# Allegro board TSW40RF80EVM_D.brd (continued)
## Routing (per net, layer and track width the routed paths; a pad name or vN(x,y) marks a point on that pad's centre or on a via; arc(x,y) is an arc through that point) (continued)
V1: length 82.4
  TOP w0.203: U29.1 22.45,60.68 v3(22.53,60.76) ; U30.1 v3(22.4,58.39)
  L4_SIG w0.127: v3(22.53,60.76) 22.53,58.52 v3(22.4,58.39) 22.4,57.94 24.72,55.62 24.72,48.53 v1(25.65,47.6)
  L6_SIG w0.127: JP3.1 79.51,51.23 78.73,52.01 69.38,52.01 69.15,51.78 69.15,51.75 68.95,51.55 68.92,51.55 68.81,51.44 66.14,51.44 62.51,47.8 58.85,47.8 58.04,46.99 56.29,46.99 55.02,48.26 50.87,48.26 50.68,48.07 50.31,48.07 50.12,48.26 47.75,48.26 47.35,47.85 43.99,47.85 43.1,46.96 43.1,45.49 41.05,43.43 41.05,43.41 39.7,42.06 32.56,42.06 32.13,42.49 32.11,42.49 31.29,43.31 26.06,43.31 25.22,44.15 25.22,44.88 25.98,45.64 25.98,47.27 v1(25.65,47.6)
  BOTTOM w0.127: R38.2 79.52,51.26 JP3.1
V2: length 78.9
  TOP w0.127: v1(23.72,48.41) 23.75,48.44 28.32,48.44 31.62,45.14 38.4,45.14 38.71,44.83 38.71,44.48 39.17,44.02 43.71,44.02 44.78,42.95 44.78,42.37 45.09,42.06 48.79,42.06 49.2,42.47 58.7,42.47 61.54,39.62 64.54,39.62 64.85,39.93 71.65,39.93 74.22,42.49 74.22,45.59 75.23,46.61 78.93,46.61 JP3.3
  TOP w0.203: U30.5 v3(22.05,56.59) ; U29.5 v3(22.12,58.9)
  L4_SIG w0.127: v3(22.12,58.9) 22.02,58.8 22.02,58.22 21.67,57.86 21.67,56.97 v3(22.05,56.59) 23.24,55.4 23.24,48.9 v1(23.72,48.41)
  BOTTOM w0.127: R39.2 79.46,47.14 JP3.3
V3: length 87.6
  TOP w0.203: v3(23.83,58.19) 24.11,57.91 U28.1 ; v3(23.62,60.83) 24.16,60.29 U27.1
  L4_SIG w0.127: v3(23.62,60.83) 23.62,58.39 v3(23.83,58.19) 24.49,57.53 24.49,56.77 25.15,56.11 25.15,49 v1(25.2,48.95)
  L6_SIG w0.127: v1(25.2,48.95) 24.74,48.49 24.74,40.94 25.27,40.41 25.27,39.12 26.39,38 27.18,38 27.51,38.33 28.12,38.33 28.47,37.97 32.26,37.97 32.74,37.49 38.51,37.49 39.73,36.27 43.97,36.27 46.76,39.07 52.04,39.07 52.4,39.42 78.94,39.42 80.01,40.49 80.01,43.33 JP7.1
  BOTTOM w0.127: R214.2 81.04,44.37 JP7.1
V4: length 75.7
  TOP w0.127: JP7.3 80.13,39.45 65.28,39.45 65,39.17 60.63,39.17 57.7,42.1 49.44,42.1 49.02,41.68 44.96,41.68 44.27,42.37 44.27,42.95 43.61,43.61 41.02,43.61 40.51,43.1 39,43.1 38.73,43.36 38.73,43.68 38.35,44.07 32.11,44.07 28.17,48.01 v1(26.37,48.01)
  TOP w0.203: U27.5 v3(25.78,59.94) ; U28.5 v3(25.78,57.56)
  L4_SIG w0.127: v1(26.37,48.01) 26.06,48.31 26.06,50.11 26.48,50.54 26.48,55.97 26.48,55.98 26.48,56.34 26.48,56.35 26.48,56.68 25.78,57.38 v3(25.78,57.56) 25.25,58.09 25.25,59.55 25.65,59.94 v3(25.78,59.94)
  BOTTOM w0.127: R213.2 81.04,40.39 JP7.3
V5: length 90
  TOP w0.203: v3(27.79,58.75) 27.78,58.74 U4.1 ; v3(28.07,60.68) 28.06,60.67 U3.1
  L4_SIG w0.127: v1(27.48,34.54) 27.48,35.74 29.77,38.02 29.77,40.51 28.12,42.16 28.12,47.07 28.32,47.27 28.32,57.48 27.79,58.01 v3(27.79,58.75) 28.07,59.03 v3(28.07,60.68)
  L6_SIG w0.127: v1(27.48,34.54) 31.05,34.54 32.25,35.75 32.27,35.75 32.97,36.45 37.34,36.45 38.1,35.69 51.89,35.69 55.12,38.91 69.77,38.91 73.23,35.46 78.21,35.46 79.5,36.75 81.84,36.75 82.54,37.46 JP8.1
  BOTTOM w0.127: JP8.1 82.67,37.47 R216.2
V6: length 81.1
  TOP w0.127: JP8.3 82.61,33.53 81.33,33.53 77.39,37.47 73.56,37.47 72.11,38.91 65.81,38.91 65.53,38.63 60.45,38.63 57.84,41.25 50.67,41.25 50.55,41.12 49.76,41.12 49.56,41.33 44.68,41.33 43.8,42.2 43.8,42.84 43.56,43.08 41.1,43.08 40.72,42.7 40.21,42.7 39.29,41.78 33.81,41.78 33.58,41.55 31.11,41.55 30.63,42.04 30.63,44.98 28.07,47.55 v1(26.97,47.55)
  TOP w0.203: U3.5 v3(27.41,59.31) ; U4.5 v3(27.43,56.95)
  L4_SIG w0.127: v3(27.41,59.31) 27.15,59.56 26.79,59.56 26.43,59.2 26.43,58.43 27.43,57.43 v3(27.43,56.95) 27.79,56.59 27.79,53.88 27.97,53.7 27.97,53.42 27.79,53.24 27.79,49.5 26.97,48.69 v1(26.97,47.55)
  BOTTOM w0.127: JP8.3 82.67,33.45 R215.2
1P8V:
  vias: v1(32.72,10.69) v1(32.72,9.63) v1(33.71,10.69) v1(33.71,9.63) v1(34.75,10.72) v1(34.75,9.65) v1(35.71,10.72) v1(35.71,9.65) v1(75.54,10.97) v1(75.54,9.98) v1(75.56,8.94) v1(75.56,7.98) v1(76.61,10.97) v1(76.61,9.98) v1(76.63,8.94) v1(76.63,7.98)
3P3VAUX: length 15.9
  L8_SIG w0.127: v1(149.96,19.81) 150.55,20.4 150.55,21.67 151.89,23.01 151.89,23.65 153.59,25.35 153.85,25.35 155.09,26.59 155.09,32.56 v1(155.68,33.15)
+1P0V_ANA: length 63.7
  L3_PWR_SIG w0.305: v1(15.05,24.07) 15.25,24.07 15.27,24.05
  L10_PWR_SIG w0.102: v1(15.05,26.47) 15.3,26.47 15.7,26.87 16.13,26.87 16.26,27 16.26,27.43 16.48,27.66 16.79,27.66 17.07,27.94 17.07,29.22
  L10_PWR_SIG w0.127: 17.07,29.22 17.59,29.74 22.25,29.74 23.34,28.65 47.62,28.65 48.13,28.14 48.13,27.51 50.24,25.4 50.39,25.4 52.1,23.7 52.91,23.7 55.04,21.56 55.04,21.08 55.68,20.45 56.29,20.45 59.46,17.27 59.46,8.86 60.55,7.77 v1(60.55,6.81)
  vias: v1(15.06,31.88) v1(16.26,32.99) v1(43.21,14.43) v1(43.21,13.41) v1(44.35,14.43) v1(44.35,13.41) v1(45.49,14.43) v1(45.49,13.41) v1(46.63,14.43) v1(46.63,13.41) v1(47.78,14.43) v1(47.78,13.41)
+1P0V_CLK: length 1.2
  L10_PWR_SIG w0.305: v1(15.85,25.67) v1(16.65,25.67)
  BOTTOM w0.305: C66.1 15.85,24.87 v1(15.85,24.87) ; C53.1 16.66,25.68 v1(16.65,25.67) ; v1(15.85,25.67) 15.88,25.69 C65.1 ; C54.1 16.66,24.86 v1(16.65,24.87)
  vias: v1(17.45,23.27) v1(17.45,22.47) v1(19.05,20.87) v1(31.45,6.99) v1(31.5,8) v1(32.44,8) v1(32.38,6.99) v1(33.4,6.99) v1(33.45,8) v1(34.54,6.99) v1(34.59,8) v1(35.74,8) v1(35.69,6.99)
+1P0V_DIG: length 7.2
  L3_PWR_SIG w0.102: 21.84,25.48 21.64,25.27 21.29,25.27 21.08,25.48 21.06,25.48 20.85,25.27 20.5,25.27 20.32,25.45 20.27,25.45 20.09,25.27 19.68,25.27 19.61,25.35 19.51,25.35 ; 18.08,24.49 17.86,24.71 17.86,25.04 18.11,25.3
  BOTTOM w0.305: v1(19.05,26.47) v1(18.25,25.67) v1(19.05,24.87) v1(18.25,24.07)
  vias: v1(38.48,10.92) v1(38.48,9.78) v1(39.62,10.92) v1(39.62,9.78) v1(40.89,10.92) v1(40.89,9.78) v1(42.16,10.92) v1(42.16,9.78) v1(43.43,10.92) v1(43.43,9.78)
+1P0V_VDDL1: length 3.4
  L3_PWR_SIG w0.102: 18.95,27.69 19.23,27.69 19.46,27.91 19.46,28.27 ; 17.58,26.11 17.65,26.11 17.86,26.31 17.86,26.62 17.75,26.72 17.75,26.85 ; 18.26,26.87 18.41,26.87 18.64,27.1 18.64,27.36
  BOTTOM w0.305: v1(17.45,24.87) 17.45,24.88 C62.1 ; v1(21.45,25.67) 21.6,25.52 21.6,25.46 ; C61.1 17.45,25.75 v1(17.45,25.67) ; v1(21.45,26.47) 21.58,26.6 C49.1
  vias: v1(36.88,14.45) v1(36.88,13.56) v1(36.88,12.57) v1(36.88,11.71) v1(37.77,14.45) v1(37.77,13.56) v1(37.77,12.57) v1(37.77,11.71)
A_IN: length 14.2
  TOP w0.381: C160.1 12.7,47.86 arc(11.01,46.73) 9.02,46.33 J9.1
ADC_CLK: length 1.4
  TOP w0.381: J8.1 C153.1
ADC_CLKINM: length 1.5
  TOP w0.203: U2.28 30.31,58.3 R229.1
  TOP w0.305: C428.2 R229.1
ADC_CLKINP: length 1.5
  TOP w0.203: U2.27 30.31,58.8 R229.2
  TOP w0.305: C427.2 R229.2
ADC_LKXEN: length 0.7
  TOP w0.254: U28.6 25.5,58.22 C434.1
ADC_LKXEP: length 0.7
  TOP w0.254: C433.1 25.45,60.55 U27.6
ADC_LXEN: length 0.6
  TOP w0.254: C432.1 22.99,56.95 U30.6
ADC_LXEP: length 0.6
  TOP w0.254: C431.1 23.03,59.29 U29.6
ADC_RESET: length 98.3
  TOP w0.127: v1(59.49,49.05) 59.03,49.05 55.44,52.64 49.09,52.64 47.96,51.51 v1(47.96,51.26) ; v1(38.43,50.83) 38.43,51.13 37.69,51.87 37.69,53.04 37.29,53.44 U2.48 ; v1(97.08,8.89) 97.11,8.92 SW2.2
  L4_SIG w0.127: v1(97.08,8.89) 97.08,10.62 96.32,11.38 96.32,19.94 95.73,20.52 87.51,20.52 86.82,21.22 86.82,25.3 86.33,25.78 86.33,31.93 85.27,32.99 v3(85.27,36.58) 85.27,36.59 84.71,37.15 84.71,37.87 83.67,38.91 79.4,38.91 76.25,42.06 67.77,42.06 61.21,48.62 59.92,48.62 v1(59.49,49.05)
  BOTTOM w0.127: v1(47.96,51.26) 47.75,51.46 43.21,51.46 42.93,51.18 38.79,51.18 v1(38.43,50.83)
ADC_SCLK: length 75.8
  TOP w0.127: U2.6 v3(37.79,63.57)
  L6_SIG w0.127: v1(81.1,67.11) 81.05,67.06 80.57,67.06 78.74,65.23 42.16,65.23 40.04,63.1 38.26,63.1 v3(37.79,63.57)
  BOTTOM w0.127: v3(86.13,39.17) 84.07,41.22 84.07,50.29 83.31,51.05 83.31,56.34 81.65,58 81.65,58.66 82.25,59.26 82.25,60.4 81.92,60.73 81.92,62 81.74,62.18 81.74,63.83 81.1,64.46 v1(81.1,67.11)
ADC_SDIO: length 76
  TOP w0.127: U2.5 38.29,63.82 38.18,63.93 v3(38.18,64.44)
  L6_SIG w0.127: v3(38.18,64.44) 38.58,64.03 40.03,64.03 41.73,65.74 78.21,65.74 v1(79.63,67.16)
  BOTTOM w0.127: v3(85.27,38.08) 84.86,38.08 83.06,39.88 83.06,50.67 82.46,51.27 82.46,54.52 80.11,56.87 80.11,58.75 79.65,59.21 79.65,61.7 80.14,62.18 80.14,63.96 79.88,64.21 79.88,66.9 v1(79.63,67.16)
ADC_SDO: length 79.6
  TOP w0.127: v1(35.1,64.92) 35.29,64.73 U2.11
  L6_SIG w0.127: v1(78.38,67.16) 77.97,67.58 76.62,67.58 76.43,67.39 36.96,67.39 36.17,66.6 36.17,65.99 v1(35.1,64.92)
  BOTTOM w0.127: v3(85.27,37.58) 84.75,37.58 82.55,39.78 82.55,50.36 81.98,50.93 81.98,53.73 78.97,56.74 78.97,58.17 78.42,58.71 78.42,62.22 78.85,62.65 78.85,63.44 78.56,63.73 78.56,66.98 v1(78.38,67.16)
ADC_SEN: length 75.9
  TOP w0.127: U2.7 37.29,64.09 v1(37.57,64.36)
  L6_SIG w0.127: v1(37.57,64.36) 37.73,64.53 37.75,64.53 38.93,65.71 39.57,65.71 40.72,66.85 76.96,66.85 v1(77.24,67.13)
  BOTTOM w0.127: v1(77.24,67.13) 77.24,63.65 76.8,63.21 76.8,60.97 77.42,60.35 77.42,57 81.05,53.37 81.05,51.09 82.04,50.1 82.04,39.75 84.63,37.16 85.19,37.16 v3(85.27,37.08)
ADC_SYNC_N: length 128.9
  L6_SIG w0.127: v1(146.76,44.53) 146.56,44.32 145.26,44.32 144.83,44.75 144.83,44.81 144.53,45.11 144.47,45.11 143.1,46.48 143.1,53.11 137.82,58.39 136.58,58.39 135.94,57.76 134.21,57.76 133.15,58.83 46.71,58.83 43.59,55.7 40.87,55.7 40.81,55.64 40.8,55.64 40.28,55.12 32.92,55.12 32.13,54.33 31.57,54.33 31.51,54.28 v3(31.14,54.28)
  BOTTOM w0.102: v1(146.76,44.53) 146.18,43.94 J14.G13
ADC_SYNC_P: length 128.9
  L6_SIG w0.127: v3(31.14,54.8) 31.52,54.79 31.55,54.76 31.95,54.76 32.74,55.55 40.08,55.55 40.61,56.08 40.64,56.08 40.69,56.13 43.38,56.13 46.51,59.26 133.33,59.26 134.39,58.19 135.76,58.19 136.4,58.83 138,58.83 143.54,53.29 143.54,48.62 143.65,48.51 143.83,48.51 143.94,48.39 143.94,48.24 143.83,48.12 143.65,48.12 143.54,48.01 143.54,46.66 144,46.19 144.16,46.19 144.31,46.34 144.46,46.34 144.58,46.23 144.58,46.07 144.43,45.92 144.43,45.77 144.65,45.54 144.73,45.54 145.26,45.01 145.26,44.93 145.44,44.75 145.97,44.75 146.18,44.96 v1(146.18,45.21)
  BOTTOM w0.102: J14.G12 v1(146.18,45.21)
ADC_SYSREFN: length 27.6
  TOP w0.203: U2.34 30.94,55.3 30.79,55.44 29.92,55.44 29.88,55.47 v1(29.64,55.47)
  L6_SIG w0.127: v1(35.23,50.37) 35.08,50.52 35.08,51.23 34.19,52.12 32.38,52.12 30.89,50.62 30.89,49 30.07,48.18 30.07,45.95 29.51,45.39 29.18,45.39 29,45.57 28.8,45.57 28.62,45.39 28.3,45.39 27.91,45.77 27.91,46.58 28.03,46.69 28.16,46.69 28.27,46.8 28.27,46.96 28.16,47.07 28.03,47.07 27.91,47.19 27.91,52.67 28.98,53.74 28.98,54.44 29.09,54.56 29.15,54.56 29.26,54.67 29.26,54.82 29.15,54.94 29.09,54.94 28.98,55.05 28.98,55.35 29.2,55.56 29.55,55.56 v1(29.64,55.47)
  BOTTOM w0.203: R99.2 35.23,49.76 v1(35.23,50.37)
ADC_SYSREFP: length 27.6
  TOP w0.203: U2.33 30.06,55.8 29.78,56.08 v1(29.64,56.08)
  L6_SIG w0.127: v1(34.53,50.39) 34.65,50.51 34.65,51.05 34.51,51.19 34.2,51.19 34.08,51.32 34.08,51.62 34.01,51.69 32.56,51.69 31.32,50.44 31.32,48.82 30.51,48 30.51,45.77 29.69,44.96 28.12,44.96 27.48,45.59 27.48,52.85 28.55,53.92 28.55,55.53 29.02,55.99 29.55,55.99 v1(29.64,56.08)
  BOTTOM w0.203: v1(34.53,50.39) 34.53,49.74 R96.2
AIN+: length 4.1
  TOP w0.381: C162.1 T5.1 T4.3 R55.2
AIN-: length 4.1
  TOP w0.381: C158.1 T5.3 T4.1 R54.2
AINM: length 9.9
  TOP w0.305: U2.41 33.79,53
  TOP w0.381: 33.79,53 33.77,52.98 33.77,52.26 33.3,51.79 32.78,51.79 32.62,51.95 32.62,52.07 32.46,52.22 32.24,52.22 31.87,51.85 31.28,51.85 30.84,52.3 30.3,52.3 29.79,51.79 29.18,51.79 28.14,52.83 T5.4 C158.2
AINP: length 10
  TOP w0.305: U2.42 34.29,53.27 34.3,53.26 34.3,52.84
  TOP w0.381: 34.3,52.84 34.3,52.06 33.53,51.28 29.13,51.28 28.14,50.29 T5.6 C162.2
ALARM: length 9.1
  TOP w0.102: v1(17.45,27.27) 17.04,27.69 17.04,29.22
  TOP w0.127: 17.04,29.22 15.35,30.91 13.72,30.91 TP3.1
ATEST: length 13
  L8_SIG w0.102: 13.92,22.05 16.97,22.05 17.34,21.67 v1(17.45,21.67)
  L8_SIG w0.127: TP15.1 6.17,25.27 9.4,22.05 11.79,22.05 11.99,22.25 12.34,22.25 12.55,22.05 13.92,22.05
B_IN: length 15.3
  TOP w0.381: J10.1 6.13,60.33 arc(8.21,60.74) 9.98,61.92 14.96,66.9 C164.1
BIN+: length 4.1
  TOP w0.381: R56.2 T6.1 T7.3 C163.1
BIN-: length 4.1
  TOP w0.381: C167.1 T7.1 T6.3 R57.2
BINM: length 9.9
  TOP w0.305: 33.78,64.79 33.82,64.75 33.82,63.47 U2.14
  TOP w0.381: 33.78,64.79 33.32,65.25 32.58,65.25 32.42,65.1 32.42,64.98 32.26,64.82 32.04,64.82 31.89,64.98 31.89,65.1 31.73,65.25 31.19,65.25 30.76,64.82 30.22,64.82 29.79,65.25 29.15,65.25 28.16,64.26 T7.6 C167.2
BINP: length 9.9
  TOP w0.305: 34.29,64.94 U2.13
  TOP w0.381: C163.2 T7.4 28.14,66.8 29.18,65.76 33.55,65.76 34.29,65.02 34.29,64.94
CAR_SYSREF_M: length 4
  BOTTOM w0.203: R86.1 27.97,39.8 R89.1 28.97,39.8 29.13,39.65 29.59,39.65 30.17,39.07 31.57,39.07 U7.4
CAR_SYSREF_P: length 4
  BOTTOM w0.203: R85.1 27.97,39.14 R90.1 28.97,39.14 29.13,39.29 29.44,39.29 30.02,38.71 31.56,38.71 U7.3
CAR_SYSREFM: length 148.6
  L8_SIG w0.127: v1(27.33,39.78) 26.89,39.78 26.8,39.69 26.63,39.69 25.9,40.42 25.9,40.57 26.01,40.69 26.01,40.84 25.9,40.96 25.74,40.96 25.63,40.84 25.48,40.84 25.2,41.12 25.2,45.09 25.15,45.14 25.15,45.16 24.74,45.57 24.74,47.9 24.85,48.01 25.01,48.01 25.12,48.12 25.12,48.28 25.01,48.39 24.85,48.39 24.74,48.5 24.74,49.12 25.31,49.69 25.33,49.69 26.67,51.03 27.09,51.03 27.2,50.92 27.2,50.78 27.31,50.67 27.47,50.67 27.58,50.78 27.58,50.92 27.69,51.03 37.69,51.03 37.95,51.28 39.04,51.28 39.19,51.13 40.41,51.13 42,52.72 44.42,52.72 47.17,55.47 47.85,55.47 48.31,55.01 48.31,54.05 48.34,54.03 48.34,54.03 48.82,53.54 49.58,53.54 50.06,54.03 50.06,54.05 50.07,54.05 50.07,55.2 50.34,55.47 50.7,55.47 50.96,55.22 50.96,54.05 50.98,54.03 50.98,54.03 51.46,53.54 52.22,53.54 52.7,54.03 52.7,54.05 52.71,54.05 52.71,55.2 52.98,55.47 53.34,55.47 53.6,55.22 53.6,54.05 53.62,54.03 53.62,54.03 54.1,53.54 54.86,53.54 55.35,54.03 55.35,54.05 55.35,54.05 55.35,55.07 55.75,55.47 137.31,55.47 144.6,48.18 144.63,48.18 144.64,48.17 146.02,48.17 146.15,48.04 v1(146.15,47.75)
CAR_SYSREFP: length 148.7
  L8_SIG w0.127: v1(146.15,49.02) 146.15,48.73 146.04,48.62 144.81,48.62 142.58,50.84 142.56,50.84 137.49,55.91 55.55,55.91 54.91,55.27 54.91,54.23 54.66,53.98 54.31,53.98 54.05,54.23 54.05,55.4 53.54,55.91 52.78,55.91 52.27,55.4 52.27,54.23 52.02,53.98 51.66,53.98 51.41,54.23 51.41,55.4 50.9,55.91 50.14,55.91 49.63,55.4 49.63,54.23 49.38,53.98 49.02,53.98 48.77,54.23 48.77,55.22 48.74,55.22 48.06,55.91 46.96,55.91 44.22,53.16 41.81,53.16 40.21,51.56 39.4,51.56 39.24,51.71 37.72,51.71 37.47,51.46 26.49,51.46 25.15,50.12 25.14,50.12 24.31,49.3 24.31,45.36 24.77,44.91 24.77,40.92 25.27,40.41 25.29,40.41 25.45,40.25 25.45,40.23 26.44,39.24 26.82,39.24 26.89,39.17 v1(27.33,39.17)
CE: length 4.7
  BOTTOM w0.305: JP5.2 69.98,41.1 71.55,42.67 71.55,44.37 v1(71.65,44.48) 71.56,44.57 U5.1
CLK_LAO_0M: length 132.2
  L8_SIG w0.127: v1(32.84,33.02) 32.94,32.92 32.94,32.16 33.53,31.57 33.53,27.56 34.24,26.85 116.81,26.85 117.6,27.63 117.6,29.13 125.73,37.26 127.05,37.26 129.9,40.11 129.9,42.19 130.84,43.13 131.5,43.13 136.68,48.31 136.68,49.22 138.97,51.51 139.01,51.51 139.22,51.71 v1(139.78,51.71)
  BOTTOM w0.102: 141.86,52.02 141.87,52.02 141.95,52.1 146.05,52.1 146.15,52 J14.G7
  BOTTOM w0.203: v1(139.78,51.71) 140.08,52.02 141.86,52.02
CLK_LAO_0P: length 132.2
  L8_SIG w0.127: v1(138.91,52.52) 138.91,52.05 138.84,51.98 138.83,51.97 138.7,51.85 136.25,49.4 136.25,48.49 131.32,43.56 130.66,43.56 129.46,42.37 129.46,40.29 126.87,37.69 125.55,37.69 117.17,29.31 117.17,28.82 117.06,28.71 117.03,28.71 116.92,28.6 116.92,28.44 117.03,28.33 117.06,28.33 117.17,28.22 117.17,27.81 116.64,27.28 34.44,27.28 33.96,27.76 33.96,28.21 34.16,28.41 34.16,28.59 33.96,28.79 33.96,31.78 33.38,32.36 33.38,32.92 v1(33.48,33.02)
  BOTTOM w0.102: 141.86,52.37 141.87,52.37 141.95,52.29 145.97,52.29 146.15,52.48 J14.G6
  BOTTOM w0.203: v1(138.91,52.52) 139.05,52.37 141.86,52.37
CLKIN0_N: length 2
  BOTTOM w0.203: U7.38 40.86,42.7 42.72,42.7 42.72,42.7 C206.2
CLKIN0_P: length 2.1
  BOTTOM w0.203: U7.37 40.87,43.05 42.57,43.05 C204.2
CLKIN1N: length 6.3
  BOTTOM w0.203: U7.35 41.63,44.14 41.7,44.21 42.13,44.21 42.82,44.9 42.82,46.59 43.58,47.35 43.92,47.35 R234.1 C384.2
CLKIN1P: length 6.3
  BOTTOM w0.203: U7.34 41.63,44.64 41.7,44.56 41.99,44.56 42.47,45.05 42.47,46.74 43.43,47.7 43.92,47.7 R234.2 C383.2
CLKLA_0M: length 3.3
  BOTTOM w0.203: R118.1 32.82,33.65 R119.1 33.03,34.51 33.03,35.9 32.96,35.97 U7.63
CLKLA_0P: length 3.3
  BOTTOM w0.203: U7.62 33.46,35.97 33.39,35.9 33.39,34.41 R117.1 33.5,33.65 R115.1
CP1: length 27.5
  TOP w0.203: v1(62.89,40.23) 62.46,40.23 59.77,42.93 48.84,42.93 48.64,43.13 45.21,43.13 44.68,43.66 44.68,44.65 43.61,45.72 40.21,45.72 v3(39.97,45.96)
  BOTTOM w0.305: C198.1 40.11,47.32 40.11,46.46 39.97,46.32 v3(39.97,45.96)
  vias: v1(63.53,40.23)
CP2: length 1.3
  TOP w0.203: C202.1 39.95,39.01 v3(40.31,38.66)
  BOTTOM w0.203: v3(40.31,38.66) 40.34,38.63 U7.46
CPOUT: length 16.4
  L6_SIG w0.203: v1(65.33,45.92) 66.67,45.92 67.41,46.66 68,46.66 68.29,46.96 68.29,48.43 68.56,48.69 71.15,48.69 71.83,49.38 76.05,49.38 v1(76.89,48.54)
  BOTTOM w0.305: v1(76.89,48.54) C193.1 R68.1 ; U5.12 65.33,45.93 v1(65.33,45.92)
DA0N: length 115.6
  TOP w0.203: C111.2 46.25,59.13 133.93,59.13 147.04,46.02 153.23,46.02 153.64,45.61 153.64,44.84 153.23,44.42 152.7,44.42 152.5,44.22 v1(152.5,43.94)
DA0P: length 115.6
  TOP w0.203: C110.2 46.25,58.78 133.78,58.78 146.89,45.67 147.81,45.67 147.99,45.49 147.99,45.34 148.17,45.16 148.42,45.16 148.6,45.34 148.6,45.49 148.78,45.67 149.56,45.67 149.74,45.49 149.74,45.31 149.92,45.14 150.17,45.14 150.35,45.31 150.35,45.49 150.53,45.67 153.09,45.67 153.29,45.47 153.29,44.98 153.09,44.78 152.7,44.78 152.5,44.98 v1(152.5,45.21)
DA1N: length 117
  TOP w0.203: v1(153.77,41.4) 153.77,41.54 154.06,41.83 154.41,41.83 154.81,42.24 154.81,43.07 154.4,43.48 151.66,43.48 151.61,43.54 146.84,43.54 132.87,57.51 46.25,57.51 C124.2
DA1P: length 117
  TOP w0.203: C123.2 46.25,57.15 132.72,57.15 146.69,43.18 150.21,43.18 150.39,43 150.39,42.62 150.57,42.44 150.82,42.44 151,42.62 151,43 151.18,43.18 151.46,43.18 151.51,43.13 154.25,43.13 154.46,42.93 154.46,42.39 154.26,42.19 153.97,42.19 153.77,42.39 v1(153.77,42.67)
DA2N: length 116.3
  TOP w0.203: C126.2 46.25,55.88 131.9,55.88 146.25,41.53 152.76,41.53 153.54,40.74 153.54,39.76 153.13,39.34 152.73,39.34 152.5,39.12 v1(152.5,38.86)
DA2P: length 116.3
  TOP w0.203: v1(152.5,40.13) 152.5,39.93 152.73,39.7 152.98,39.7 153.19,39.9 153.19,40.59 152.61,41.17 151.79,41.17 151.62,40.99 151.62,40.54 151.44,40.36 151.18,40.36 151.01,40.54 151.01,40.99 150.83,41.17 146.1,41.17 131.75,55.52 46.25,55.52 C125.2
DA3N: length 117.8
  TOP w0.203: C135.2 46.25,54.18 131.14,54.18 146.91,38.4 154.4,38.4 154.81,37.99 154.81,37.19 154.4,36.78 153.97,36.78 153.77,36.58 v1(153.77,36.32)
DA3P: length 117.8
  TOP w0.203: C127.2 46.25,53.82 130.99,53.82 146.77,38.05 150.9,38.05 151.08,37.87 151.08,37.44 151.26,37.26 151.51,37.26 151.69,37.44 151.69,37.87 151.87,38.05 154.25,38.05 154.46,37.85 154.46,37.34 154.25,37.13 153.97,37.13 153.77,37.34 v1(153.77,37.59)
DAC_ALT_SYNC_N: length 143
  L8_SIG w0.102: v1(19.05,21.67) 19.48,21.25 19.48,20.52 19.05,20.09 19.05,19.7
  L8_SIG w0.127: v1(147.42,35.05) 147.42,35.34 147.55,35.47 147.82,35.47 148.29,35 148.29,34.14 147.62,33.48 147.47,33.48 147.19,33.75 147.03,33.75 146.92,33.64 146.92,33.48 147.2,33.21 147.2,33.05 135.95,21.8 135.79,21.8 135.63,21.96 135.47,21.96 135.36,21.85 135.36,21.69 135.52,21.53 135.52,21.37 134.94,20.79 26.91,20.79 25.12,19 20.93,19 20.82,19.11 20.82,19.37 20.71,19.48 20.55,19.48 20.44,19.37 20.44,19.11 20.33,19 19.23,19 19.05,19.18 19.05,19.7
DAC_ALT_SYNC_P: length 143
  L8_SIG w0.102: 18.62,19.7 18.62,19.72 18.64,19.75 18.64,21.28 v1(18.25,21.67)
  L8_SIG w0.127: v1(147.42,36.32) 147.42,36.03 147.55,35.9 147.99,35.9 148.72,35.18 148.72,33.96 135.12,20.36 28.59,20.36 28.19,19.96 28.01,19.96 27.62,20.36 27.09,20.36 25.3,18.57 19.05,18.57 18.62,19 18.62,19.7
DAC_CLKOUTN: length 55.8
  TOP w0.203: U4.4 27.08,57.26 26.77,56.95 v3(26.77,56.77)
  L6_SIG w0.127: v1(18.95,16.46) 18.95,16.05 18.87,15.98 18.87,15.75 19.13,15.49 19.93,15.49 20.05,15.61 20.05,15.69 20.16,15.8 20.32,15.8 20.43,15.69 20.43,15.61 20.54,15.49 22.4,15.49 23.04,16.13 23.39,16.13 23.96,16.69 23.96,16.85 23.86,16.95 23.86,17.1 23.97,17.22 24.13,17.22 24.22,17.12 24.38,17.12 25.15,17.88 25.15,18.42 25.03,18.53 24.9,18.53 24.79,18.64 24.79,18.8 24.9,18.91 25.03,18.91 25.15,19.02 25.15,30.12 23.04,32.23 23.04,36.42 22.68,36.78 22.68,51 26.6,54.92 26.6,55.08 26.33,55.35 26.33,55.51 26.44,55.62 26.59,55.62 26.87,55.35 27.03,55.35 27.84,56.16 27.84,57.43 27.57,57.7 26.9,57.7 26.77,57.57 v3(26.77,56.77)
DAC_CLKOUTP: length 55.7
  TOP w0.203: v3(26.77,59.05) 26.77,59.26 27.06,59.54 U3.4
  L6_SIG w0.127: v3(26.77,59.05) 26.77,58.25 26.9,58.13 27.75,58.13 28.27,57.61 28.27,55.98 23.11,50.82 23.11,36.96 23.47,36.6 23.47,32.41 25.58,30.3 25.58,17.7 23.57,15.7 23.22,15.7 22.58,15.06 18.94,15.06 18.43,15.57 18.43,16.09 18.34,16.18 v1(18.34,16.46)
DAC_RESET: length 126
  TOP w0.102: 94.01,38.33 93.52,38.33 v1(93.45,38.4)
  TOP w0.127: SW1.2 104.17,8.92 R30.2 v1(104.14,9.91) ; 94.01,38.33 R329.2
  L4_SIG w0.127: v1(93.45,38.4) 93.45,37.8 94.08,37.16 96.01,37.16 97.61,35.56 97.61,25.7 98.15,25.17 98.15,21.01 99.01,20.14 99.01,15.04 v1(104.14,9.91)
  L6_SIG w0.102: v1(16.65,27.27) 16.66,27.27 17.07,27.69 17.07,29.22
  L6_SIG w0.127: v1(17.65,34.21) 17.07,33.63 17.07,29.22
  BOTTOM w0.127: v1(93.45,38.4) 92.76,38.4 90.27,35.92 84.76,35.92 84.28,36.4 79.93,36.4 78.84,35.31 72.9,35.31 69.6,32 33.1,32 32.49,32.61 19.1,32.61 17.65,34.06 v1(17.65,34.21)
DAC_SCLK: length 18.1
  L8_SIG w0.127: v3(84.56,42.32) 83.97,42.9 83.97,43.05 83.72,43.31 74.98,43.31 69.77,38.1 v1(69.77,37.41)
DAC_SDENB: length 23
  L8_SIG w0.127: v1(69.75,34.14) 69.67,34.14 69.22,34.59 69.22,38.3 74.78,43.87 79.27,43.87 80.75,45.34 83.79,45.34 v3(84.58,44.55)
DAC_SDIO: length 16.9
  L8_SIG w0.127: v3(83.62,42.29) 82.35,42.29 81.46,41.4 73.94,41.4 70.22,37.68 70.22,36.77 v1(69.77,36.32)
DAC_SDO: length 23
  L8_SIG w0.127: v3(83.59,44.58) 83.24,44.22 83.24,43.76 83.39,43.61 84.43,43.61 84.91,43.13 84.91,41.45 82.96,39.5 72.72,39.5 70.59,37.36 70.59,36.09 v1(69.75,35.26)
DAC_SYNC_N: length 141.9
  L8_SIG w0.102: v1(21.45,21.67) 21.46,21.67 22.03,21.67 22.68,22.31 23.4,22.31 23.41,22.33 23.43,22.33
  L8_SIG w0.127: v1(147.42,46.48) 147.42,46.77 147.55,46.9 147.97,46.9 148.29,46.58 148.29,46.29 148.17,46.18 147.94,46.18 147.83,46.07 147.83,45.91 147.94,45.8 148.17,45.8 148.29,45.69 148.29,44.93 147.9,44.55 147.74,44.55 147.67,44.62 147.51,44.62 147.4,44.51 147.4,44.35 147.47,44.28 147.47,44.12 125.68,22.33 125.11,22.33 125,22.44 125,22.67 124.89,22.78 124.73,22.78 124.62,22.67 124.62,22.44 124.51,22.33 24.15,22.33 24.04,22.44 24.04,22.72 23.93,22.83 23.77,22.83 23.66,22.72 23.66,22.44 23.55,22.33 23.43,22.33
DAC_SYNC_P: length 141.9
  L8_SIG w0.102: 23.43,21.89 23.4,21.89 23.39,21.91 22.85,21.91 22.2,21.26 21.07,21.26 v1(20.65,21.67)
  L8_SIG w0.127: 23.43,21.89 125.86,21.89 148.72,44.75 148.72,46.76 148.15,47.33 147.55,47.33 147.42,47.46 v1(147.42,47.75)
DACCLK_IN: length 14.7
  TOP w0.381: J1.1 5.63,6.22 arc(7.14,6.52) 8.42,7.38 C1.1
DACCLK_N: length 2.6
  TOP w0.203: C361.1 16.46,17.8 16.46,19.88 U1.A9
DACCLK_P: length 2.6
  TOP w0.203: C360.1 16.1,17.77 16.1,19.82 U1.A10
DACCLK_SE: length 1.5
  TOP w0.381: R1.2 R2.1 14.15,14.94 C1.2
DACCLKSE: length 3.9
  TOP w0.381: U1.A12 14.12,19.94 R3.1 R1.1
DB0N: length 113.6
  TOP w0.203: C137.2 46.25,60.4 135.79,60.4 149.26,46.94 153.57,46.94 153.77,46.74 v1(153.77,46.48)
DB0P: length 113.6
  TOP w0.203: v1(153.77,47.75) 153.77,47.5 153.57,47.29 149.4,47.29 135.94,60.76 46.25,60.76 C136.2
DB1N: length 109.6
  TOP w0.203: v1(151.23,51.56) 151.23,51.82 151.03,52.02 146.7,52.02 136.7,62.03 46.25,62.03 C140.2
DB1P: length 109.6
  TOP w0.203: C138.2 46.25,62.38 136.84,62.38 146.85,52.37 151.03,52.37 151.23,52.58 v1(151.23,52.83)
DB2N: length 113.5
  TOP w0.203: C148.2 46.25,63.65 137.7,63.65 143.18,58.17 145.6,58.17 149.21,54.56 151.42,54.56 152.48,53.5 152.48,52.43 152.89,52.02 153.57,52.02 153.77,51.82 v1(153.77,51.56)
DB2P: length 113.5
  TOP w0.203: C141.2 46.25,64.01 137.85,64.01 143.33,58.53 145.75,58.53 149.36,54.91 151.57,54.91 152.83,53.65 152.83,52.58 153.03,52.37 153.57,52.37 153.77,52.58 v1(153.77,52.83)
DB3N: length 112.6
  TOP w0.203: v1(153.77,56.64) 153.77,56.9 153.57,57.1 152.16,57.1 151.69,57.57 151.69,59.59 151.22,60.06 146.62,60.06 146.09,60.59 143.17,60.59 138.49,65.28 46.25,65.28 C150.2
DB3P: length 112.6
  TOP w0.203: v1(153.77,57.91) 153.77,57.66 153.57,57.45 152.31,57.45 152.04,57.72 152.04,59.74 151.36,60.42 146.76,60.42 146.23,60.95 143.32,60.95 138.63,65.63 46.25,65.63 C149.2
DCLKOUT2N: length 3.9
  BOTTOM w0.203: U7.16 30.8,45.14 30.73,45.06 30.32,45.06 29.84,45.54 29.25,45.54 29.1,45.69 R72.1 28.09,45.69 C197.1
DCLKOUT2P: length 3.9
  BOTTOM w0.203: C196.1 28.09,45.03 R71.1 29.1,45.03 29.25,45.19 29.7,45.19 30.18,44.71 30.73,44.71 30.8,44.64 U7.15
DCLKOUT4N: length 4
  BOTTOM w0.203: C208.1 37.13,49.63 R95.1 36.98,48.85 36.98,47.77 36.39,47.19 36.39,46.87 36.46,46.8 U7.25
DCLKOUT4P: length 4
  BOTTOM w0.203: U7.24 35.96,46.8 36.04,46.87 36.04,47.33 36.62,47.92 36.62,48.85 R94.1 36.47,49.62 C207.1
DM: length 4.7
  L8_SIG w0.152: J15.2 133.25,15.8 134.95,17.5 134.95,18.81 135.18,19.04 135.18,19.05 v1(135.36,19.23)
DP: length 4.7
  L8_SIG w0.152: v1(134.72,19.23) 134.42,18.92 134.11,18.92 133.12,19.91 132.59,19.91 132.36,19.68 132.36,18.06 J15.3
DP0_C2M_N: length 143
  L6_SIG w0.127: v1(31.9,31.55) 32.34,31.55 32.43,31.64 33.06,31.64 33.63,31.06 33.63,27.71 34.52,26.82 116.92,26.82 118.64,28.55 125.55,28.55 128.85,31.85 128.85,32.82 132.61,36.58 140.49,36.58 148.41,44.5 148.41,48.36 148.18,48.59 148.18,52.1 148.34,52.25 148.34,54.76 150.63,57.06 151.1,57.06 151.23,56.93 v1(151.23,56.64)
DP0_C2M_P: length 143
  L6_SIG w0.127: v1(31.9,32.16) 32.34,32.16 32.43,32.07 33.24,32.07 34.06,31.24 34.06,27.89 34.7,27.25 116.74,27.25 118.46,28.98 125.37,28.98 128.42,32.03 128.42,33 132.43,37.01 140.31,37.01 147.98,44.68 147.98,48.18 147.75,48.41 147.75,52.27 147.9,52.43 147.9,54.94 150.46,57.49 151.1,57.49 151.23,57.62 v1(151.23,57.91)
DP1_C2M_N: length 124.8
  TOP w0.203: C22.1 32.33,30.53 32.45,30.4 145.77,30.4 146.04,30.12 147.96,30.12 148.62,30.78 154.28,30.78 154.51,31.01 154.51,31.5 154.31,31.7 153.97,31.7 153.77,31.5 v1(153.77,31.24)
DP1_C2M_P: length 126
  TOP w0.203: C20.1 32.33,29.92 32.45,30.05 145.62,30.05 145.9,29.77 148.11,29.77 148.77,30.43 154.43,30.43 154.86,30.86 154.86,31.64 154.45,32.05 153.97,32.05 153.77,32.26 v1(153.77,32.51)
DP2_C2M_N: length 123
  TOP w0.203: C23.1 32.33,28.3 32.45,28.42 142.63,28.42 143.92,27.13 150.09,27.13 150.6,26.62 153.57,26.62 153.77,26.42 v1(153.77,26.16)
DP2_C2M_P: length 123
  TOP w0.203: v1(153.77,27.43) 153.77,27.18 153.57,26.97 150.75,26.97 150.24,27.48 144.07,27.48 142.77,28.78 32.45,28.78 32.33,28.91 C21.1
DP3_C2M_N: length 127.8
  TOP w0.203: v1(153.77,21.08) 153.77,21.34 153.97,21.54 154.46,21.54 154.91,22 154.91,22.66 154.33,23.24 152.94,23.24 152.25,22.56 144.88,22.56 140.23,27.2 32.4,27.2 32.27,27.33 C24.1
DP3_C2M_P: length 127.8
  TOP w0.203: v1(153.77,22.35) 153.77,22.1 153.97,21.89 154.31,21.89 154.56,22.14 154.56,22.51 154.18,22.89 153.09,22.89 152.4,22.2 151.25,22.2 151.07,22.02 151.07,21.59 150.89,21.41 150.64,21.41 150.46,21.59 150.46,22.02 150.28,22.2 144.73,22.2 140.08,26.85 32.4,26.85 32.27,26.72 C25.1
DP4_C2M_N: length 128.4
  TOP w0.203: v1(153.77,16) 153.77,16.26 153.97,16.46 154.33,16.46 154.74,16.87 154.74,17.75 154.33,18.16 153.14,18.16 152.4,17.42 144.98,17.42 138.45,23.95 32.4,23.95 32.27,24.08 C15.1
DP4_C2M_P: length 128.4
  TOP w0.203: C14.1 32.27,23.47 32.4,23.6 138.3,23.6 144.83,17.07 151.31,17.07 151.49,16.89 151.49,16.46 151.67,16.28 151.92,16.28 152.1,16.46 152.1,16.89 152.28,17.07 152.55,17.07 153.28,17.81 154.18,17.81 154.38,17.6 154.38,17.02 154.18,16.81 153.97,16.81 153.77,17.02 v1(153.77,17.27)
DP5_C2M_N: length 130.2
  TOP w0.203: C10.1 32.27,20.83 32.4,20.7 136.7,20.7 145.18,12.22 152.15,12.22 153.21,13.28 154.51,13.28 155.09,12.7 155.09,11.81 154.66,11.38 153.97,11.38 153.77,11.18 v1(153.77,10.92)
DP5_C2M_P: length 130.2
  TOP w0.203: v1(153.77,12.19) 153.77,11.94 153.97,11.73 154.52,11.73 154.74,11.96 154.74,12.55 154.36,12.93 153.36,12.93 152.11,11.68 152.11,11.23 151.94,11.05 151.68,11.05 151.51,11.23 151.51,11.68 151.33,11.86 145.03,11.86 136.55,20.35 32.4,20.35 32.27,20.22 C11.1
DP6_C2M_N: length 124.3
  TOP w0.203: v1(152.5,13.46) 152.5,13.72 152.3,13.92 145.52,13.92 137.46,21.97 32.4,21.97 32.27,21.84 C12.1
DP6_C2M_P: length 124.3
  TOP w0.203: C13.1 32.27,22.45 32.4,22.33 137.61,22.33 145.66,14.27 152.3,14.27 152.5,14.48 v1(152.5,14.73)
DP7_C2M_N: length 123.6
  TOP w0.203: v1(152.5,18.54) 152.5,18.8 152.3,19 145.49,19 139.27,25.22 32.4,25.22 32.27,25.1 C17.1
DP7_C2M_P: length 123.6
  TOP w0.203: C16.1 32.27,25.7 32.4,25.58 139.42,25.58 145.64,19.35 152.3,19.35 152.5,19.56 v1(152.5,19.81)
EEDATA: length 4.6
  TOP w0.127: U12.3 98.87,48.94 R159.1 99.35,48.96 100.27,49.87 v3(100.27,51.03)
EXT_ADCCLKINM: length 2.5
  TOP w0.381: C430.1 R84.2 18.02,56.74 T3.3
EXT_ADCCLKINP: length 2.5
  TOP w0.381: T3.1 18.02,59.54 R83.1 C429.1
EXTIO: length 4.1
  L6_SIG w0.102: 13.92,21.29 15.47,21.29 v3(15.85,21.67)
  L6_SIG w0.127: v3(12.27,20.32) 13.24,21.29 13.92,21.29
FMC_ADC_RESET: length 57.3
  L10_PWR_SIG w0.127: v1(149.28,40.69) 149.33,40.64 149.33,38.86 148.69,38.23 144.68,38.23 143.28,39.62 143.28,41.43 140.61,44.09 118.57,44.09 118.21,43.74 105.08,43.74 104.06,42.72 101.17,42.72 99.87,41.43 v1(99.77,41.43)
  BOTTOM w0.102: v1(149.28,40.69) 149.96,41.38 J14.D15
FMC_ADC_SCK: length 53.4
  L4_SIG w0.127: v1(151.56,42.16) 150.11,43.61 147.68,43.61 144.68,40.61 144.68,39.29 144.42,39.04 144.42,39.04 144.27,38.89 142.32,38.89 140.12,41.08 140.1,41.08 139.84,41.34 139.84,41.36 139.19,42.01 138.17,42.01 138.16,42 137.79,42 136.38,43.41 134.93,43.41 134.76,43.24 134.74,43.24 134.64,43.14 133.92,43.14 133.71,43.36 127.36,43.36 126.88,42.88 121.16,42.88 120.6,42.32 119.81,42.32 119.56,42.57 115.47,42.57 114.55,41.66 v3(105.11,41.66)
  BOTTOM w0.102: v1(151.56,42.16) 151.23,42.49 J14.C14
FMC_ADC_SDIO: length 54.7
  L4_SIG w0.127: v3(103,40.61) 103.11,40.5 112.02,40.5 112.84,39.69 113.22,39.69 113.41,39.5 114.68,39.5 114.91,39.73 115.98,39.73 117.02,38.68 135,38.68 135.33,39.01 140.11,39.01 140.26,38.86 140.97,38.86 141.43,38.4 145.06,38.4 145.36,38.71 145.36,39.85 147.98,42.47 147.98,42.75 148.41,43.18 149.5,43.18 150.44,42.24 v1(150.44,40.67)
  BOTTOM w0.102: v1(150.44,40.67) 151.18,41.4 J14.C15
FMC_ADC_SDO: length 54.1
  L4_SIG w0.127: v1(150.63,37) 149.43,38.2 147.22,38.2 145.59,36.58 116.94,36.58 116.31,35.94 109.98,35.94 107.87,38.05 103.58,38.05 103.07,37.54 102.62,37.54 101.96,38.2 101.96,39.22 v3(102.51,39.78)
  BOTTOM w0.102: J14.C18 v1(150.63,37)
FMC_ADC_SEN: length 52.4
  TOP w0.127: R317.1 102.01,38.94 v1(102.69,38.25)
  L4_SIG w0.127: v1(102.69,38.25) 103.91,39.47 107.37,39.47 108.38,38.46 112.29,38.46 112.65,38.81 114.73,38.81 115.32,38.23 138.56,38.23 138.81,38.48 140.34,38.48 140.82,38 145.47,38 145.85,38.38 145.85,39.34 148.67,42.16 v1(149.38,42.16)
  BOTTOM w0.102: J14.D14 149.89,42.67 v1(149.38,42.16)
FMC_CTRL1: length 162.1
  L8_SIG w0.127: v2(150.65,28.09) 150.65,28.75 154.94,33.04 154.94,59.31 151.71,62.53 147.24,62.53 146.69,61.98 144.55,61.98 144.27,62.26 40.64,62.26 40.27,61.89 31.69,61.89 31.22,62.36 v1(28.78,62.36)
  BOTTOM w0.102: J14.C26 151.23,27.51 v2(150.65,28.09)
FMC_CTRL2: length 163.9
  L8_SIG w0.127: v1(28.78,61.75) 28.85,61.82 30.73,61.82 31.98,60.58 40.36,60.58 40.89,61.11 43.87,61.11 44.37,60.6 139.14,60.6 139.55,61.01 146.81,61.01 147.73,60.1 152.5,60.1 153.14,59.46 153.14,43.94 152.04,42.85 152.04,41.94 153.14,40.84 153.14,33.78 149.45,30.1 149.45,28.25 150.62,27.08 v2(150.62,25.53)
  BOTTOM w0.102: J14.C27 151.23,26.14 v2(150.62,25.53)
FMC_DAC_RESET: length 56.7
  L4_SIG w0.127: v1(148.69,36.32) 148.16,36.86 146.94,36.86 146.18,36.09 117.22,36.09 116.1,34.98 112.32,34.98 112.14,34.8 103.68,34.8 100.76,37.72 v3(94.28,37.72)
FMC_DAC_SCK: length 66.4
  L4_SIG w0.127: v1(116.18,37.13) 138.76,37.13 v1(139.45,37.82)
  L6_SIG w0.127: v1(116.18,37.13) 115.51,37.81 112.64,37.81 112.5,37.95 109.39,37.95 107.92,39.42 104.55,39.42 103.73,40.23 101.7,40.23 101.04,40.89 99.75,40.89 99.52,40.67 97.38,40.67 96.9,40.18 93.8,40.18 92.94,41.05 90.78,41.05 90.17,40.44 85.55,40.44 84.56,41.43 v3(84.56,41.71)
  BOTTOM w0.102: 141.86,38.3 145.01,38.3 145.44,38.73 145.44,39.42 J14.G16
  BOTTOM w0.127: v1(139.45,37.82) 139.93,38.3 141.86,38.3
FMC_DAC_SDENB: length 67.2
  L4_SIG w0.127: v1(144.22,39.47) 144.22,40.16 141.66,42.72 139.47,42.72 138.12,44.07 119.73,44.07 119.72,44.08 119.35,44.08 119.34,44.07 108.15,44.07 106.43,45.8 98.48,45.8 97.41,44.73 90.83,44.73 89.46,46.1 84.63,46.1 84.07,45.54 84.07,44.45 v3(84.58,43.94)
  BOTTOM w0.102: J14.H16 v1(144.22,39.47)
FMC_DAC_SDIO: length 68
  L6_SIG w0.127: v1(115.54,36.45) 115.07,35.98 114.16,35.98 114.11,36.03 114.09,36.03 113.83,36.29 113.83,36.31 113.25,36.89 109.51,36.89 108.38,38.02 105.28,38.02 103.81,39.5 100.99,39.5 100.69,39.8 97.16,39.8 96.7,39.34 93.07,39.34 92.91,39.5 86.39,39.5 86.32,39.57 85.72,39.57 v3(83.62,41.68)
  L10_PWR_SIG w0.127: v1(115.54,36.45) 136.45,36.45 v1(141.5,41.5)
  BOTTOM w0.102: 141.86,41.15 142.09,40.92 145.67,40.92 J14.G15
  BOTTOM w0.127: 141.86,41.15 v1(141.5,41.5)
FMC_DAC_SDO: length 69.2
  L10_PWR_SIG w0.127: v1(144.88,38.86) 144.93,38.91 144.93,40.64 138.91,46.66 136.04,46.66 135.56,47.14 116.15,47.14 114.78,45.77 112.32,45.77 111.94,46.15 109.86,46.15 109.4,45.69 105.61,45.69 105.28,46.02 97.46,46.02 96.47,45.03 90.17,45.03 89.03,46.18 84.99,46.18 84.1,45.29 84.1,44.48 v3(83.59,43.97)
FMC_LMK_CSB: length 65.4
  BOTTOM w0.102: 87.81,52.43 87.06,51.68 v3(86.63,51.68) ; 139.12,48.92 141.4,48.92 141.94,48.39 146.33,48.39 146.48,48.24 148.2,48.24 J14.E10
  BOTTOM w0.127: 139.12,48.92 138.07,48.92 133.25,53.75 89.13,53.75 87.81,52.43
FMC_LMK_SCK: length 72.8
  BOTTOM w0.102: 83.72,52.43 83.72,51.38 85.3,49.81 v3(85.75,49.81) ; 137.39,55.93 140.03,53.29 140.39,53.29 140.7,53.59 141.42,53.59 141.65,53.82 141.96,53.82 142.15,53.63 142.15,53.63 142.19,53.59 147.93,53.59 J14.E6
  BOTTOM w0.127: 83.72,52.43 83.72,53.92 85.72,55.93 137.39,55.93
FMC_LMK_SDIO: length 71.1
  BOTTOM w0.102: v1(148.69,51.56) 148.21,51.08 141.15,51.08 140.56,50.5 140.16,50.5 ; 84.66,52.43 84.66,51.05 85.41,50.31 v3(85.75,50.31)
  BOTTOM w0.127: 84.66,52.43 84.66,53.59 86.4,55.33 134.15,55.33 138.99,50.5 140.16,50.5
FMC_LMK_SDO: length 69
  BOTTOM w0.102: v1(148.69,49.02) 148.18,49.53 146.14,49.53 145.64,50.03 145.29,50.03 144.74,49.48 143.82,49.48 143.81,49.49 142.15,49.49 142.13,49.48 138.33,49.48 ; 85.32,52.43 85.09,52.2 85.09,51.05 85.34,50.81 v3(85.75,50.81)
  BOTTOM w0.127: 85.32,52.43 87.17,54.28 133.53,54.28 138.33,49.48
FMC_LMX_CSB: length 71.8
  L10_PWR_SIG w0.127: v3(85.75,49.31) 85.19,48.75 85.19,47.24 85.62,46.81 94.56,46.81 94.97,47.22 97.03,47.22 98.27,48.46 110.13,48.46 111.3,47.29 115.49,47.29 115.87,47.68 142.21,47.68 148.69,41.2 v1(148.69,40.13)
  BOTTOM w0.102: v1(148.69,40.13) v1(148.16,39.6)
FMC_LMX_SCK: length 68.9
  L4_SIG w0.127: v1(134.54,49.1) 138.3,49.1 142.8,44.6 v2(144.32,44.6)
  L8_SIG w0.127: v1(134.54,49.1) 133.43,50.22 119.96,50.22 119.95,50.23 115.26,50.23 115.25,50.22 113.94,50.22 113.54,49.81 110.69,49.81 109.68,48.79 99.49,48.79 96.52,45.82 95.02,45.82 93.98,46.86 86.26,46.86 85.83,47.29 85.83,47.73 v3(85.75,47.81)
  BOTTOM w0.102: v2(144.32,44.6) 144.37,44.65 146.28,44.65 146.76,45.14 146.76,45.24 147.27,45.75 148.11,45.75 148.64,45.21 J14.E12
FMC_LMX_SDIO: length 71
  L4_SIG w0.127: v1(128.98,46.69) 138.68,46.69 141.3,44.07 147.37,44.07 147.7,44.4 v1(149.2,44.4)
  L8_SIG w0.127: v3(85.75,48.31) 85.14,47.7 85.14,47.29 85.95,46.48 88.47,46.48 89.87,45.09 96.52,45.09 99.87,48.44 108.15,48.44 109.5,47.09 112.67,47.09 113.54,47.96 122.43,47.96 123.7,46.69 v1(128.98,46.69)
  BOTTOM w0.102: v1(149.2,44.4) 148.74,43.94 J14.E13
FMC_LMX_SDO: length 71.6
  L8_SIG w0.127: v1(129.24,45.95) 123.7,45.95 122.1,47.55 115.65,47.55 113.84,45.75 111.93,45.75 111.55,46.13 110.29,46.13 110.13,45.97 98.04,45.97 96.65,44.58 89.81,44.58 88.21,46.18 85.65,46.18 84.73,47.09 84.73,47.79 v3(85.75,48.81)
  BOTTOM w0.102: 141.86,43.18 147.6,43.18 147.9,42.88 147.9,42.19 J14.E15
  BOTTOM w0.127: v1(129.24,45.95) 136.98,45.95 137.44,45.49 139.17,45.49 141.48,43.18 141.86,43.18
FPGA_CLK1_N: length 123.4
  L6_SIG w0.127: v1(140.23,54.36) 139.78,54.36 135.97,50.54 135.97,47.83 131.24,43.1 130.76,43.1 129.82,42.16 129.82,40.03 127.08,37.29 125.32,37.29 116.31,28.27 39.55,28.27 39.42,28.4 38.58,28.4 37.88,29.1 37.88,33.35 v1(37.77,33.45)
  BOTTOM w0.102: 141.86,54.56 141.88,54.56 141.97,54.64 142.24,54.64 142.34,54.54 J14.K5
  BOTTOM w0.203: v1(140.23,54.36) 140.44,54.56 141.86,54.56
FPGA_CLK1_P: length 123.4
  L6_SIG w0.127: v1(38.42,33.45) 38.33,33.36 38.33,29.29 38.79,28.83 39,28.83 39.11,28.94 39.11,28.97 39.22,29.08 39.38,29.08 39.49,28.97 39.49,28.94 39.73,28.7 116.13,28.7 116.87,29.44 116.87,29.57 117.11,29.81 117.24,29.81 125.14,37.72 126.9,37.72 129.39,40.21 129.39,42.34 130.58,43.54 131.06,43.54 135.53,48.01 135.53,50.72 139.48,54.66 v1(139.48,55.11)
  BOTTOM w0.102: J14.K4 142.34,54.93 142.24,54.83 141.97,54.83 141.88,54.91 141.86,54.91
  BOTTOM w0.203: v1(139.48,55.11) 139.67,54.91 141.86,54.91
FPGA_CLK1N: length 3.1
  BOTTOM w0.203: C217.1 37.85,34.14 37.85,34.64 R106.1 37.75,34.83 38.15,35.23 38.15,35.68 38.46,36 U7.52
FPGA_CLK1P: length 3.1
  BOTTOM w0.203: U7.51 38.97,36.37 38.82,36.23 38.82,35.85 38.51,35.53 38.51,35.09 38.44,35.02 R105.1 38.24,34.53 38.24,34.24 C216.1
FPGA_CLK2_N: length 124
  L6_SIG w0.127: v1(137.82,56.94) 137.37,56.94 134.32,53.9 130.51,53.9 127.15,50.55 127.15,46.96 122.53,42.34 122.53,40.13 118.64,36.25 117.68,36.25 116.13,34.69 116.13,30.83 115.29,30 40.84,30 40.18,30.66 40.18,31.57 40.44,31.83 40.44,33.36 v1(40.34,33.45)
  BOTTOM w0.102: 141.86,57.1 141.88,57.1 141.97,57.18 143.51,57.18 143.61,57.08 J14.J3
  BOTTOM w0.203: 141.86,57.1 137.98,57.1 v1(137.82,56.94)
FPGA_CLK2_P: length 124
  L6_SIG w0.127: v1(137.06,57.7) 137.06,57.25 134.14,54.33 130.33,54.33 126.72,50.72 126.72,47.14 122.1,42.52 122.1,40.31 118.46,36.68 117.51,36.68 115.7,34.87 115.7,31.98 115.57,31.85 115.57,31.6 115.7,31.47 115.7,31.01 115.16,30.48 42.16,30.48 42.1,30.54 42.1,30.57 41.99,30.68 41.83,30.68 41.72,30.57 41.72,30.54 41.66,30.48 41.02,30.48 40.64,30.86 40.64,31.37 40.89,31.62 40.89,33.35 v1(40.99,33.45)
  BOTTOM w0.102: 141.86,57.45 141.88,57.45 141.97,57.37 143.51,57.37 143.61,57.47 J14.J2
  BOTTOM w0.203: v1(137.06,57.7) 137.31,57.45 141.86,57.45
FPGA_CLK2N: length 3.2
  BOTTOM w0.203: C226.1 40.33,34.08 R110.1 40.33,35.23 40.12,35.43 39.96,35.43 39.67,35.71 39.67,35.9 39.54,36.03 39.54,36.28 39.47,36.35 U7.50
FPGA_CLK2P: length 3.2
  BOTTOM w0.203: C224.1 41.01,34.08 R111.1 41.01,35.06 39.89,36.18 39.89,36.31 39.97,36.38 U7.49
FTDI_TCK: length 11.4
  TOP w0.127: v3(86.59,41.07) 86.59,41.05 85.9,40.36 82.55,40.36 81.53,41.38 77.31,41.38 J5.2
FTDI_TDI: length 14.7
  TOP w0.127: J5.4 76.93,38.99 81.31,38.99 82.19,39.88 85.88,39.88 86.39,40.39 86.56,40.39 86.97,40.79 86.97,42.29 86.74,42.52 85.98,42.52 85.62,42.16 v3(85.58,42.16)
FTDI_TDO: length 13.9
  L6_SIG w0.127: J5.6 77.4,36.43 79.96,38.99 81.46,38.99 82.58,40.11 82.58,42.65 83.34,43.41 84.84,43.41 v3(85.58,42.66)
FTDI_TMS: length 16.3
  L8_SIG w0.127: J5.8 80.49,38.56 84.28,38.56 86.44,40.72 86.74,40.72 86.94,40.92 86.94,42.27 86.69,42.52 86.22,42.52 v3(85.58,43.16)
FTDI_TRSTB: length 21.4
  L6_SIG w0.127: J5.10 83.51,32.43 84.43,33.35 89.26,33.35 94.22,38.32 v3(95.27,38.32)
GA0: length 5.7
  L8_SIG w0.127: v2(151.84,18.01) 152.02,17.83 153.7,17.83 v1(155.68,19.81)
  BOTTOM w0.102: J14.C34 151.23,17.4 v2(151.84,18.01)
GA1: length 10.8
  L8_SIG w0.127: v1(149.96,16) 149.96,15.67 150.6,15.04 150.6,14.73 151.05,14.27 151.41,14.27 152.04,13.64 152.04,13.28 152.4,12.93 154.43,12.93 155.24,12.12 155.24,9.45 v1(155.68,9.02)
GPIO1: length 14.5
  TOP w0.127: U2.19 31.14,62.81 v1(31.14,62.81)
  L4_SIG w0.127: v1(30.38,49.38) 30.68,49.68 30.68,52.53 30.38,52.83 30.38,53.19 30.66,53.47 30.91,53.47 31.5,54.05 31.5,62.41 31.14,62.76 v1(31.14,62.81)
GPIO2: length 10.5
  TOP w0.127: 40.94,58.34 v3(41.07,58.32) 41.05,58.3 U2.63 40.94,58.34
  L4_SIG w0.127: v1(42.09,48.95) 40.59,50.44 40.59,57.78 41.07,58.27 v3(41.07,58.32)
GTX_CLKM: length 148.6
  L8_SIG w0.127: v1(27.94,37.87) 27.5,37.87 27.41,37.78 26.53,37.78 26.23,38.08 26.23,38.24 26.35,38.36 26.35,38.52 26.24,38.63 26.08,38.63 25.96,38.51 25.8,38.51 23.14,41.17 23.14,41.46 23.25,41.57 23.43,41.57 23.55,41.68 23.55,41.84 23.43,41.95 23.25,41.95 23.14,42.06 23.14,49.68 23.53,50.07 23.69,50.07 23.76,50 23.92,50 24.03,50.11 24.03,50.27 23.96,50.34 23.96,50.5 27.46,54 30.15,54 30.78,54.64 30.78,54.96 31.04,55.22 40.38,55.22 40.8,55.64 40.81,55.64 40.95,55.78 43.61,55.78 44.88,57.05 135.36,57.05 136.5,58.19 137.87,58.19 140.89,55.17 143.31,55.17 143.93,54.55 147.01,54.55 147.06,54.5 149.86,54.5 149.96,54.39 v1(149.96,54.1)
GTX_CLKP: length 148.6
  L8_SIG w0.127: v1(27.94,37.26) 27.5,37.26 27.43,37.34 26.34,37.34 22.71,40.97 22.71,49.89 23.5,50.68 23.52,50.68 27.28,54.43 29.97,54.43 30.35,54.81 30.35,55.14 30.86,55.65 40.2,55.65 40.62,56.07 40.63,56.07 40.77,56.21 43.43,56.21 44.7,57.48 135.18,57.48 136.32,58.62 138.05,58.62 141.07,55.6 143.48,55.6 144.11,54.98 147.19,54.98 147.24,54.93 149.8,54.93 149.84,54.97 149.85,54.97 149.96,55.08 v1(149.96,55.37)
GTXCLKM: length 3.3
  BOTTOM w0.203: C201.1 28.57,37.9 R77.1 29.34,37.74 29.94,37.74 30.26,38.06 30.86,38.06 30.93,38.13 U7.2
GTXCLKP: length 3.3
  BOTTOM w0.203: U7.1 30.93,37.63 30.86,37.7 30.4,37.7 30.09,37.39 29.34,37.39 R78.1 28.57,37.24 C199.1
IOUTA: length 8
  TOP w0.381: J3.1 6.63,31.62 arc(7.71,31.41) 8.61,30.8 R22.1 R20.1
IOUTAM: length 2.1
  TOP w0.381: C26.1 14.25,27.27 U1.K12
IOUTB: length 8
  TOP w0.381: J4.1 6.94,18.92 arc(7.72,19.08) 8.39,19.52 R25.1 9.51,20.65 R23.1
IOUTBP: length 2.1
  TOP w0.381: C27.1 14.23,23.3 U1.E12
LMK LOCKED: length 1.1
  TOP w0.127: R126.1 D4.1
LMK-CSB: length 16.1
  L8_SIG w0.127: v3(88.13,51.68) 89.07,52.63 97.79,52.63 99.16,51.26 99.16,50.55 98.45,49.83 98.45,49.4 97.43,48.38 v3(96.95,48.34)
LMK-SCK: length 4.8
  L6_SIG w0.127: v3(89,49.81) 89.93,50.74 92.9,50.74 v3(93.24,50.39)
LMK-SDIO: length 7.7
  TOP w0.127: R293.2 95.33,48.18 91.08,48.18 90.2,49.07 90.2,49.63 89.52,50.31 U32.17
LMK-SDO: length 9
  L8_SIG w0.127: v3(96.19,48.34) 95.86,48.67 95.86,50.06 95.22,50.7 92.79,50.7 92.68,50.81 v3(89,50.81)
LMK_ADC_CLKN: length 7.3
  TOP w0.203: v3(25.53,57.02) 25.34,57.21 U28.4
  BOTTOM w0.203: v3(25.53,57.02) 25.4,57.15 25.4,58.09 25.19,58.29 25.02,58.29 24.74,58.02 24.74,57.87 24.78,57.84 24.78,57.69 24.67,57.59 24.53,57.59 24.49,57.62 24.35,57.62 24.09,57.37 24.09,55.83 24.88,55.03 C448.2 L19.2
LMK_ADC_CLKP: length 7.3
  TOP w0.203: v3(25.58,59.46) 25.45,59.59 U27.4
  BOTTOM w0.203: L18.2 25.12,53.9 C447.2 24.63,54.78 23.74,55.68 23.74,57.52 25.58,59.36 v3(25.58,59.46)
LMK_CLKIN: length 15.5
  BOTTOM w0.381: C204.1 R93.1 45.02,43.26 arc(45.95,43.44) 46.73,43.96 49.65,46.88 arc(51.46,48.09) 53.59,48.51 J12.1
LMK_CSB: length 78.2
  L6_SIG w0.127: v1(32.08,48.79) 32.23,48.79 32.61,49.17 32.61,49.33 33.15,49.86 39.09,49.86 39.55,50.32 40.79,50.32 42,51.52 42,51.65 42.55,52.2 43.08,52.2 45.31,54.43 96.14,54.43 99.05,51.53 99.05,50.3 97.69,48.95 v3(96.95,48.95)
  BOTTOM w0.127: U7.18 32.96,46.46 32.49,46.94 32.28,46.94 31.65,47.57 31.65,48.36 v1(32.08,48.79)
LMK_DAC_CLKN: length 51.6
  BOTTOM w0.203: C197.2 27.36,45.57 25.66,45.57 18.37,38.28 11.51,38.28 7.34,34.11 7.34,27.74 8.94,26.14 8.94,19.36 12.81,15.49 15.42,15.49 16.47,16.55 16.47,17.42 16.68,17.63 v3(17.24,17.63)
LMK_DAC_CLKP: length 51.6
  BOTTOM w0.203: C196.2 27.3,45.21 25.81,45.21 18.52,37.92 11.66,37.92 7.7,33.96 7.7,27.89 9.3,26.29 9.3,19.51 11.67,17.13 11.93,17.13 12.13,17.33 12.38,17.33 12.56,17.16 12.56,16.9 12.36,16.7 12.36,16.45 12.95,15.85 13.99,15.85 14.17,16.03 14.17,16.31 14.35,16.48 14.6,16.48 14.78,16.31 14.78,16.03 14.96,15.85 15.27,15.85 16.12,16.7 16.12,17.42 15.91,17.62 v3(15.35,17.62)
LMK_DAC_SYSREFN: length 51.6
  BOTTOM w0.203: v1(20.75,16.13) 20.88,16 20.88,15.46 20.48,15.06 20.15,15.06 19.97,15.24 19.97,15.37 19.79,15.54 19.54,15.54 19.36,15.37 19.36,15.24 19.18,15.06 18.16,15.06 17.58,15.64 17.58,16.84 18.21,17.48 18.21,18.14 16.87,19.48 14.68,19.48 14.55,19.61 14.55,20.09 14.36,20.28 13.88,20.28 13.23,20.93 13.23,23.95 11.46,25.73 11.46,28.21 9.93,29.74 9.93,32.9 10.19,33.16 10.19,33.51 9.93,33.77 9.93,34.11 10.75,34.93 11.15,34.93 11.38,35.16 11.38,35.56 12.09,36.27 19.46,36.27 24.75,41.56 25,41.56 25.04,41.52 25.29,41.52 25.47,41.7 25.47,41.95 25.43,41.99 25.43,42.24 26.49,43.31 26.88,43.31 27.03,43.15 R81.2 28.04,43.15 R74.2
LMK_DAC_SYSREFP: length 51.6
  BOTTOM w0.203: v1(21.36,16.13) 21.23,16 21.23,15.32 20.62,14.71 18.01,14.71 17.22,15.49 17.22,16.99 17.75,17.52 17.75,18.09 16.72,19.13 14.53,19.13 12.88,20.78 12.88,21.08 12.88,23.8 11.1,25.58 11.1,28.07 9.58,29.59 9.58,34.26 11.94,36.63 19.31,36.63 26.34,43.66 26.88,43.66 27.03,43.81 R82.2 28.04,43.81 R75.2
LMK_SCK: length 72.3
  L6_SIG w0.127: v1(33.07,49.15) 33.07,48.54 33.63,47.98 33.63,47.57 34.02,47.18 39.33,47.18 43.41,51.26 46.96,51.26 47.42,50.8 50.72,50.8 52.5,52.58 58.04,52.58 58.59,53.12 59.4,53.12 59.94,52.58 63.04,52.58 63.98,53.52 70.43,53.52 71.3,52.65 93.37,52.65 93.6,52.43 93.6,50.14 v3(93.24,49.78)
  BOTTOM w0.127: U7.19 33.46,46.75 32.64,47.57 32.64,48.72 v1(33.07,49.15)
LMK_SDIO: length 71.8
  L6_SIG w0.127: v3(95.48,48.95) 95.89,49.35 95.89,50.09 95.33,50.65 94.16,50.65 93.98,50.83 93.98,52.65 92.66,53.98 45.47,53.98 40.77,49.28 39.52,49.28 39.32,49.48 34.19,49.48 v1(33.88,49.17)
  BOTTOM w0.127: U7.20 33.96,46.94 33.58,47.32 33.58,48.03 33.45,48.16 33.45,48.74 v1(33.88,49.17)
LMK_SDO: length 69.5
  L6_SIG w0.102: 83.54,46.79 87.88,46.79
  L6_SIG w0.127: 87.88,46.79 94.03,46.79 v3(96.19,48.95) ; v3(31.98,39.62) 31.98,39.65 32.49,40.16 32.49,41.17 32.89,41.58 41.15,41.58 43,43.43 49.1,43.43 49.68,44.02 65.91,44.02 66.7,43.23 71.07,43.23 71.3,43 75.87,43 79.1,46.23 82.98,46.23 83.54,46.79
LMX-CSB: length 22
  L8_SIG w0.102: v3(89,49.31) 88.73,49.58 88.09,49.58 87.76,49.91 87.76,52.2 87.99,52.43
  L8_SIG w0.127: 87.99,52.43 89.87,54.31 102.97,54.31 103.68,53.59 v3(103.68,52.48)
LMX-SCLK: length 5.6
  L4_SIG w0.102: v3(93.24,51.05) 92.25,51.05 v3(89,47.81)
LMX-SDI: length 7.1
  L8_SIG w0.127: v3(95.48,46.76) 94.49,47.75 89.97,47.75 89.41,48.31 v3(89,48.31)
LMX-SDO: length 8
  L8_SIG w0.127: v3(89,48.81) 89.55,48.81 90.12,48.23 94.72,48.23 v3(96.19,46.76)
LMX_CLKAN: length 55.9
  TOP w0.203: U30.3 21.7,58.44 v3(21.67,58.47)
  BOTTOM w0.203: v3(21.67,58.47) 21.67,59.23 21.87,59.44 23.41,59.44 29.43,65.46 55.51,65.46 55.84,65.13 56.12,65.13 56.45,65.46 56.79,65.46 66.6,55.65 66.6,55.11 66.8,54.91 67.34,54.91 67.67,54.58 67.67,54.29 67.56,54.17 C171.2
LMX_CLKAP: length 55.9
  TOP w0.203: v3(21.64,60.76) 21.75,60.65 U29.3
  BOTTOM w0.203: v3(21.64,60.76) 21.67,60.76 21.67,59.99 21.87,59.79 23.26,59.79 29.28,65.81 56.94,65.81 68.03,54.72 68.03,54.31 68.17,54.17 C170.2
LMX_CLKBN: length 21
  BOTTOM w0.203: C383.1 45.42,47.7 46.92,47.7 53.4,54.18 60.78,54.18 62.15,52.8 62.38,52.8 62.8,52.38 C184.2
LMX_CLKBP: length 21
  BOTTOM w0.203: C384.1 45.42,47.35 47.07,47.35 53.54,53.82 58.94,53.82 59.29,53.47 59.55,53.47 59.9,53.82 60.63,53.82 61.91,52.54 61.91,52.34 62.34,51.91 C181.2
LMX_CSB: length 38.2
  L4_SIG w0.127: v3(68.56,50.7) 69.18,51.32 69.18,52.01 69.57,52.4 70.05,52.4 71.3,53.64 98.09,53.64 99.24,52.5 99.35,52.5 v3(99.26,52.48) 99.75,52.96 99.75,53.19 100.23,53.67 101.97,53.67 102.51,53.12 102.51,52.65 102.69,52.48 v1(103.07,52.48)
LMX_OSCM: length 24
  BOTTOM w0.203: U5.9 67.56,43.82 67.63,43.75 67.63,43.07 67.3,42.74 66.65,42.74 66.47,42.92 66.47,43.08 66.29,43.26 66.04,43.26 65.86,43.08 65.86,42.92 65.68,42.74 50.37,42.74 50.36,42.75 49.71,42.75 48.77,41.81 47.03,41.81 46.91,41.94 C230.2
LMX_OSCP: length 23.9
  BOTTOM w0.203: C231.2 46.91,41.33 47.03,41.45 48.92,41.45 49.86,42.39 50.21,42.39 50.22,42.39 67.45,42.39 67.99,42.92 67.99,43.75 68.06,43.82 U5.8
LMX_SCLK: length 30.2
  L4_SIG w0.102: 92,52.43 92.76,51.66 v3(93.24,51.66)
  L4_SIG w0.127: 92,52.43 91.74,52.68 72.14,52.68 70.59,51.13 70.59,50.37 70.23,50.01 69.32,50.01 69.14,50.19 68.1,50.19 67.08,49.17 67.08,48.72 v3(66.29,47.93)
LMX_SDI: length 37.5
  L4_SIG w0.127: v3(95.48,46.15) 94.82,46.81 83.41,46.81 82.52,45.92 77.47,45.92 75.39,48.01 75.39,48.08 74.09,49.38 71.96,49.38 71.65,49.07 71.65,48.01 71.3,47.65 70.64,47.65 70.36,47.37 70.36,46.96 70.08,46.69 67.49,46.69 66.88,46.08 65.81,46.08 64.97,46.91 64.97,47.57 65.83,48.43 v3(66.29,48.43)
LMX_SDO: length 40.1
  L4_SIG w0.127: v3(66.27,50.52) 65.94,50.19 65.94,49.3 64.52,47.88 64.52,46.1 65.56,45.06 67.01,45.06 68.8,43.27 71.06,43.27 71.74,43.95 74.66,43.95 75.01,43.61 76.73,43.61 78.51,45.39 82.8,45.39 83.82,46.41 89.69,46.41 90.44,45.66 94.22,45.66 94.39,45.82 95.86,45.82 v3(96.19,46.15)
Net_32:
  vias: v1(20.65,22.47)
Net_115:
  vias: v1(152.5,29.97)
Net_116:
  vias: v1(152.5,28.7)
Net_117:
  vias: v1(152.5,24.89)
Net_118:
  vias: v1(152.5,23.62)
Net_138:
  vias: v1(19.05,28.07)
Net_139:
  vias: v1(18.25,28.07)
Net_140:
  vias: v1(18.25,28.87)
Net_141:
  vias: v1(18.25,27.27)
Net_224:
  vias: v1(152.5,59.18)
Net_225:
  vias: v1(152.5,35.05)
Net_226:
  vias: v1(152.5,33.78)
Net_227:
  vias: v1(151.23,47.75)
Net_229:
  vias: v1(151.23,36.32)
Net_233:
  vias: v1(151.23,13.46)
Net_237:
  vias: v1(149.96,35.05)
Net_238:
  vias: v1(149.96,33.78)
Net_240:
  vias: v1(149.96,29.97)
Net_242:
  vias: v1(149.96,26.16)
Net_243:
  vias: v1(149.96,14.73)
Net_245:
  vias: v1(149.96,9.65)
Net_246:
  vias: v1(149.96,50.29)
Net_247:
  vias: v1(149.96,49.02)
Net_248:
  vias: v1(148.69,37.59)
Net_249:
  vias: v1(148.69,57.91)
Net_254:
  vias: v1(148.69,26.16)
Net_255:
  vias: v1(148.69,24.89)
Net_256:
  vias: v1(148.69,56.64)
Net_258:
  vias: v1(148.69,21.08)
